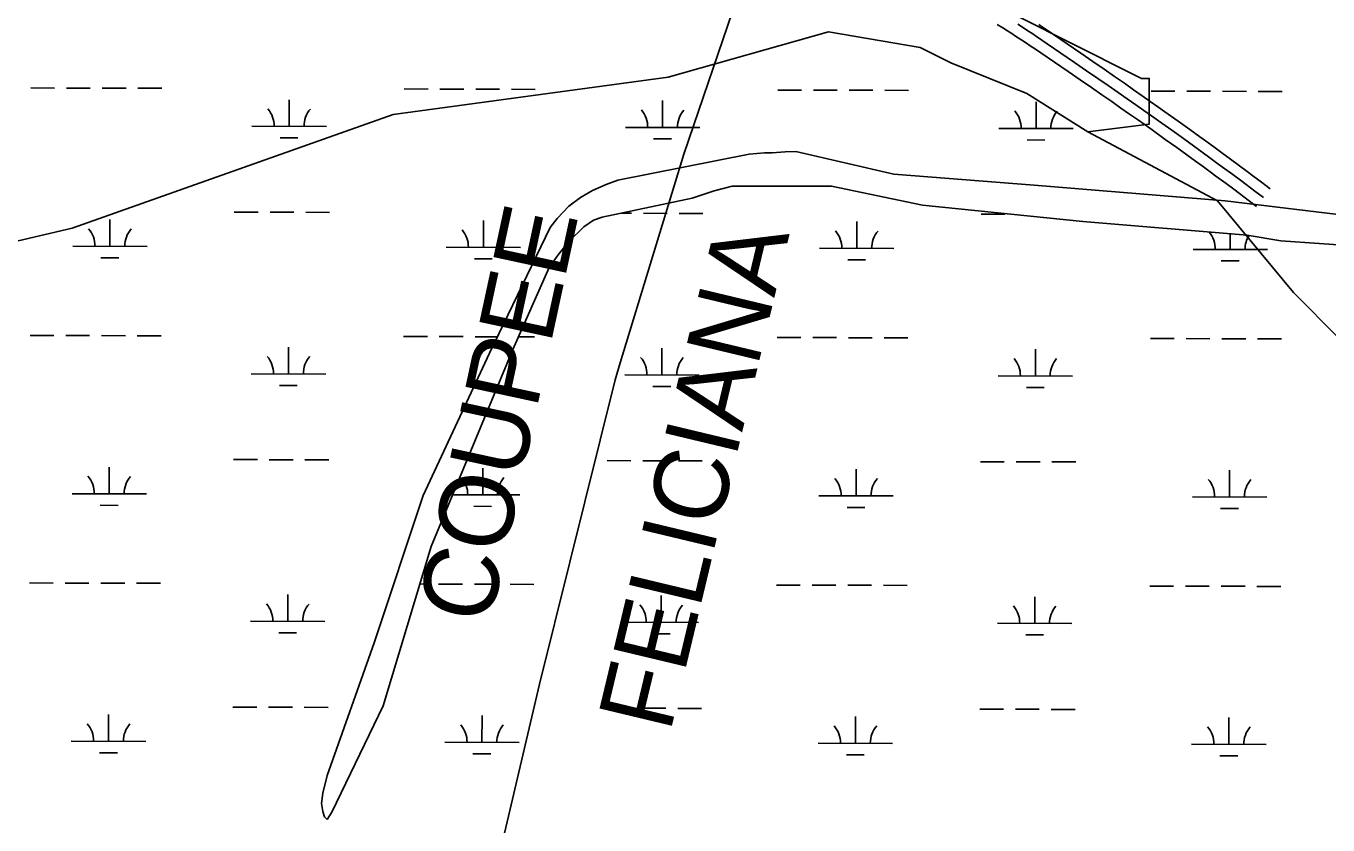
# Model space of a CAD drawing. Extents: x 3161615 to 3199515, y 867541 to 892976.
# Drawn here: x 3178180 to 3179930, y 873810 to 874884 of the extents above; entities that cross this region are included whole.
import ezdxf

# ---------------------------------------------------------------- set-up
doc = ezdxf.new("R2010")
doc.units = 0
for name, color, linetype in [('V-ROAD-CNTR', 7, 'Continuous'), ('V-TOPO-BNDY', 7, 'Continuous'), ('V-TOPO-GNAM-IDEN', 7, 'Continuous'), ('V-TOPO-SHOR', 7, 'Continuous'), ('V-WETL-SWMP', 7, 'Continuous')]:
    doc.layers.add(name, color=color, linetype=linetype)

msp = doc.modelspace()

# ---------------------------------------------------------------- linework, layer by layer
at = {"layer": 'V-ROAD-CNTR'}
for points in [[(3179485.3, 874885.7), (3179492.8, 874881), (3179499.3, 874876.9), (3179505, 874873.3), (3179509.9, 874870.1), (3179518.6, 874864.5), (3179525, 874860.3), (3179529.8, 874857.1), (3179537, 874852.3), (3179544.2, 874847.4), (3179580.9, 874822.2), (3179597, 874811.2), (3179612, 874800.8), (3179626.1, 874791.1), (3179639.3, 874781.9), (3179651.6, 874773.3), (3179663.2, 874765.2), (3179674, 874757.7), (3179684.1, 874750.5), (3179693.6, 874743.8), (3179711.3, 874731.2), (3179726.8, 874720.1), (3179740.3, 874710.4), (3179752.1, 874701.8), (3179762.5, 874694.3), (3179771.5, 874687.7), (3179779.3, 874681.9), (3179793.1, 874671.8), (3179803.3, 874664.1), (3179811, 874658.3), (3179822.5, 874649.6), (3179834, 874640.9)], [(3179513.1, 874886), (3179518.1, 874882.8), (3179526.8, 874877.1), (3179533.3, 874872.8), (3179538.2, 874869.6), (3179545.4, 874864.7), (3179552.7, 874859.8), (3179589.4, 874834.6), (3179605.5, 874823.5), (3179620.5, 874813.1), (3179634.6, 874803.4), (3179647.8, 874794.2), (3179660.2, 874785.6), (3179671.8, 874777.5), (3179682.6, 874769.9), (3179692.7, 874762.8), (3179702.2, 874756.1), (3179720, 874743.4), (3179735.6, 874732.3), (3179749.1, 874722.6), (3179761, 874714), (3179771.3, 874706.4), (3179780.3, 874699.8), (3179788.2, 874694), (3179802, 874683.8), (3179812.3, 874676.1), (3179820, 874670.3), (3179831.6, 874661.6), (3179843.1, 874652.8)], [(3179541.5, 874885.4), (3179546.5, 874882.1), (3179553.8, 874877.2), (3179561.1, 874872.2), (3179597.9, 874846.9), (3179614, 874835.9), (3179629.1, 874825.5), (3179643.2, 874815.7), (3179656.4, 874806.5), (3179668.8, 874797.9), (3179680.4, 874789.8), (3179691.2, 874782.2), (3179701.4, 874775), (3179710.9, 874768.3), (3179728.7, 874755.7), (3179744.3, 874744.5), (3179757.9, 874734.7), (3179769.8, 874726.1), (3179780.2, 874718.6), (3179789.2, 874711.9), (3179797.1, 874706.1), (3179811, 874695.8), (3179821.3, 874688.1), (3179829.1, 874682.3), (3179840.7, 874673.5), (3179852.2, 874664.7)]]:
    msp.add_lwpolyline(points, dxfattribs=at)
at = {"layer": 'V-TOPO-BNDY'}
for p, q in [((3179064.1, 874711.2), (3179152.6, 874969.8)), ((3178978.9, 874430.8), (3179064.1, 874711.2)), ((3178972, 874408), (3178978.9, 874430.8)), ((3178911.2, 874162.7), (3178972, 874408)), ((3178870.4, 873998.9), (3178911.2, 874162.7)), ((3178790.2, 873659.1), (3178870.4, 873998.9))]:
    msp.add_line(p, q, dxfattribs=at)
at = {"layer": 'V-TOPO-SHOR'}
for points in [[(3179310.9, 875132.1), (3179464.6, 875039.3), (3179464.5, 875008.5), (3179454.1, 874947), (3179474.5, 874916.1), (3179576.9, 874864.6), (3179679.4, 874813), (3179689.7, 874813), (3179689.6, 874802.7), (3179689.5, 874751.4), (3179607.4, 874741.4)], [(3178673.8, 874764.5), (3179043.3, 874814.7), (3179258.9, 874875.7), (3179382, 874854.8), (3179423, 874834.2), (3179525.4, 874792.9), (3179607.4, 874741.4), (3179781.5, 874648.5), (3179883.8, 874525.1), (3179945.2, 874463.4), (3179996.4, 874412), (3180057.8, 874381), (3180160.4, 874370.5), (3180386.1, 874369.9), (3180468.1, 874349.1), (3180519.5, 874369.5), (3180591.5, 874420.6), (3180632.7, 874502.5)], [(3178673.8, 874764.5), (3178242.4, 874611.8), (3178067.9, 874571.2), (3177842.1, 874530.8), (3177800.9, 874469.3), (3177728.9, 874418.2), (3177677.4, 874326), (3177595.1, 874244.2), (3177533.2, 874121.2), (3177481.5, 873988), (3177450.6, 873947), (3177378.3, 873793.3), (3177305.9, 873567.8), (3177233.7, 873424.4), (3177161.6, 873342.5), (3177089.6, 873270.9), (3176966.3, 873209.7), (3176915, 873189.3), (3176894.3, 873148.3), (3176857.1, 873094.3)]]:
    msp.add_lwpolyline(points, dxfattribs=at)
at = {"layer": 'V-WETL-SWMP'}
for p, q in [((3178186.6, 874800.3), (3178218.6, 874800.2)), ((3178234.6, 874800.1), (3178266.6, 874800)), ((3178282.6, 874800), (3178314.6, 874799.9)), ((3178330.6, 874799.9), (3178362.6, 874799.8)), ((3178688.5, 874798.9), (3178720.5, 874798.8)), ((3178736.5, 874798.7), (3178768.5, 874798.6)), ((3178784.5, 874798.6), (3178816.5, 874798.5)), ((3178832.5, 874798.5), (3178864.5, 874798.4)), ((3179190.4, 874797.5), (3179222.4, 874797.4)), ((3179238.4, 874797.3), (3179270.4, 874797.3)), ((3179286.4, 874797.2), (3179318.4, 874797.1)), ((3179334.4, 874797.1), (3179366.4, 874797)), ((3179692.3, 874796.1), (3179724.3, 874796)), ((3179740.3, 874796), (3179772.3, 874795.9)), ((3179788.3, 874795.8), (3179820.3, 874795.7)), ((3179836.3, 874795.7), (3179868.3, 874795.6)), ((3178533.8, 874748.5), (3178533.9, 874784.5)), ((3179035.7, 874747.2), (3179035.8, 874783.2)), ((3179537.6, 874745.8), (3179537.7, 874781.8)), ((3178483.8, 874748.7), (3178583.8, 874748.4)), ((3178985.7, 874747.3), (3179085.7, 874747)), ((3179487.6, 874745.9), (3179587.6, 874745.6)), ((3178521.7, 874733.2), (3178545.7, 874733.1)), ((3179023.7, 874731.8), (3179047.7, 874731.7)), ((3179525.6, 874730.4), (3179549.6, 874730.3)), ((3179152.1, 874711.1), (3178975.5, 874676.5)), ((3179172.8, 874713), (3179152.1, 874711.1)), ((3179183, 874713), (3179172.8, 874713)), ((3179200.4, 874714.3), (3179183, 874713)), ((3179214.8, 874714.8), (3179200.4, 874714.3)), ((3179346.7, 874684.5), (3179214.8, 874714.8)), ((3178975.5, 874676.5), (3178959.7, 874670.7)), ((3179534.9, 874669.4), (3179346.7, 874684.5)), ((3178941.3, 874662.4), (3178925.3, 874653.2)), ((3178959.7, 874670.7), (3178941.3, 874662.4)), ((3179075.6, 874651.9), (3179105, 874662.1)), ((3179105, 874662.1), (3179129.3, 874668.3)), ((3179129.3, 874668.3), (3179262.9, 874668.1)), ((3179262.9, 874668.1), (3179385.1, 874642.7)), ((3179791.6, 874648.7), (3179534.9, 874669.4)), ((3178909.9, 874641.4), (3178894.1, 874624.7)), ((3178925.3, 874653.2), (3178909.9, 874641.4)), ((3178954.4, 874626.5), (3179075.6, 874651.9)), ((3179385.1, 874642.7), (3179600.3, 874620.6)), ((3180024.4, 874620.3), (3179791.6, 874648.7)), ((3178292.9, 874587.4), (3178293, 874623.4)), ((3178460.1, 874633.3), (3178492.1, 874633.2)), ((3178508.1, 874633.2), (3178540.1, 874633.1)), ((3178556.1, 874633.1), (3178588.1, 874633)), ((3178794.8, 874586), (3178794.9, 874622)), ((3178894.1, 874624.7), (3178884.5, 874612.7)), ((3178929.8, 874613.8), (3178942.9, 874622.4)), ((3178942.9, 874622.4), (3178954.4, 874626.5)), ((3178979.9, 874631.9), (3178994, 874631.8)), ((3179010, 874631.8), (3179042, 874631.7)), ((3179058, 874631.7), (3179090, 874631.6)), ((3179296.7, 874584.6), (3179296.8, 874620.6)), ((3179463.9, 874630.5), (3179495.9, 874630.5)), ((3179600.3, 874620.6), (3179821.4, 874602.4)), ((3178884.5, 874612.7), (3178803, 874443.7)), ((3178909.9, 874593.8), (3178929.8, 874613.8)), ((3179798.6, 874583.2), (3179798.6, 874604.3)), ((3178242.9, 874587.5), (3178342.9, 874587.2)), ((3178744.8, 874586.1), (3178844.8, 874585.8)), ((3178895.3, 874575.8), (3178909.9, 874593.8)), ((3179821.4, 874602.4), (3179866.8, 874594.6)), ((3179866.8, 874594.6), (3180086.2, 874579.7)), ((3178280.8, 874572), (3178304.8, 874571.9)), ((3178782.7, 874570.6), (3178806.7, 874570.5)), ((3178883.3, 874558.8), (3178895.3, 874575.8)), ((3179246.7, 874584.7), (3179346.7, 874584.4)), ((3179284.6, 874569.2), (3179308.6, 874569.1)), ((3179748.6, 874583.3), (3179848.6, 874583.1)), ((3178834.6, 874448.6), (3178883.3, 874558.8)), ((3179786.5, 874567.8), (3179810.5, 874567.7)), ((3178185.7, 874467.6), (3178217.7, 874467.5)), ((3178233.7, 874467.4), (3178265.7, 874467.4)), ((3178281.7, 874467.3), (3178313.7, 874467.2)), ((3178329.7, 874467.2), (3178361.7, 874467.1)), ((3178687.6, 874466.2), (3178719.6, 874466.1)), ((3178735.6, 874466.1), (3178767.6, 874466)), ((3178783.6, 874465.9), (3178813.7, 874465.8)), ((3178842.2, 874465.8), (3178863.6, 874465.7)), ((3179189.5, 874464.8), (3179221.5, 874464.7)), ((3179237.5, 874464.7), (3179269.5, 874464.6)), ((3179285.5, 874464.5), (3179317.5, 874464.4)), ((3179333.5, 874464.4), (3179365.5, 874464.3)), ((3179691.4, 874463.4), (3179723.4, 874463.3)), ((3179739.4, 874463.3), (3179771.4, 874463.2)), ((3179787.4, 874463.2), (3179819.4, 874463.1)), ((3179835.4, 874463), (3179867.4, 874462.9)), ((3178532.9, 874415.9), (3178533, 874451.9)), ((3178724.7, 874184), (3178834.6, 874448.6)), ((3179034.8, 874414.5), (3179034.9, 874450.5)), ((3179536.7, 874413.1), (3179536.8, 874449.1)), ((3178803, 874443.7), (3178713.8, 874252.6)), ((3178482.9, 874416), (3178582.9, 874415.7)), ((3178984.8, 874414.6), (3179084.8, 874414.4)), ((3179486.7, 874413.2), (3179586.7, 874413)), ((3178520.8, 874400.5), (3178544.8, 874400.4)), ((3179022.7, 874399.1), (3179046.7, 874399)), ((3179524.6, 874397.7), (3179548.6, 874397.6)), ((3178292, 874254.7), (3178292, 874290.7)), ((3178459.1, 874300.6), (3178491.1, 874300.6)), ((3178507.1, 874300.5), (3178539.1, 874300.4)), ((3178555.1, 874300.4), (3178587.1, 874300.3)), ((3178793.9, 874253.3), (3178794, 874289.3)), ((3178961, 874299.3), (3178993, 874299.2)), ((3179009, 874299.1), (3179041, 874299)), ((3179057, 874299), (3179089, 874298.9)), ((3179463, 874297.9), (3179495, 874297.8)), ((3179511, 874297.7), (3179543, 874297.7)), ((3179559, 874297.6), (3179591, 874297.5)), ((3179295.8, 874251.9), (3179295.9, 874287.9)), ((3179797.7, 874250.5), (3179797.8, 874286.5)), ((3178242, 874254.8), (3178342, 874254.5)), ((3178753.5, 874253.4), (3178843.9, 874253.2)), ((3178279.9, 874239.3), (3178303.9, 874239.2)), ((3178713.8, 874252.6), (3178648.1, 874054.6)), ((3178781.8, 874237.9), (3178805.8, 874237.8)), ((3179245.8, 874252), (3179345.8, 874251.8)), ((3179283.7, 874236.5), (3179307.7, 874236.4)), ((3179747.7, 874250.7), (3179847.7, 874250.4)), ((3179785.6, 874235.1), (3179809.6, 874235.1)), ((3178660.1, 873969.5), (3178724.7, 874184)), ((3178184.8, 874134.9), (3178216.8, 874134.8)), ((3178232.8, 874134.8), (3178264.8, 874134.7)), ((3178280.8, 874134.6), (3178312.8, 874134.5)), ((3178328.8, 874134.5), (3178360.8, 874134.4)), ((3178709.5, 874133.5), (3178718.7, 874133.4)), ((3178734.7, 874133.4), (3178766.7, 874133.3)), ((3178782.7, 874133.3), (3178814.7, 874133.2)), ((3178830.7, 874133.1), (3178862.7, 874133)), ((3179188.6, 874132.1), (3179220.6, 874132)), ((3179236.6, 874132), (3179268.6, 874131.9)), ((3179284.6, 874131.9), (3179316.6, 874131.8)), ((3179332.6, 874131.7), (3179364.6, 874131.6)), ((3179690.5, 874130.7), (3179722.5, 874130.7)), ((3179738.5, 874130.6), (3179770.5, 874130.5)), ((3179786.5, 874130.5), (3179818.5, 874130.4)), ((3178531.9, 874083.2), (3178532, 874119.2)), ((3179033.9, 874081.8), (3179034, 874117.8)), ((3179535.8, 874080.4), (3179535.9, 874116.4)), ((3179834.5, 874130.3), (3179866.5, 874130.3)), ((3178481.9, 874083.3), (3178581.9, 874083.1)), ((3178983.9, 874082), (3179083.9, 874081.7)), ((3179485.8, 874080.6), (3179585.8, 874080.3)), ((3178519.9, 874067.8), (3178543.9, 874067.7)), ((3179021.8, 874066.4), (3179045.8, 874066.4)), ((3179523.7, 874065), (3179547.7, 874065)), ((3178648.1, 874054.6), (3178585.1, 873875.9)), ((3178291, 873922), (3178291.1, 873958)), ((3178458.2, 873968), (3178490.2, 873967.9)), ((3178506.2, 873967.8), (3178538.2, 873967.8)), ((3178554.2, 873967.7), (3178586.2, 873967.6)), ((3178591.4, 873826.8), (3178660.1, 873969.5)), ((3178792.9, 873920.6), (3178793, 873956.6)), ((3178960.1, 873966.6), (3178992.1, 873966.5)), ((3179008.1, 873966.5), (3179040.1, 873966.4)), ((3179056.1, 873966.3), (3179088.1, 873966.2)), ((3179462, 873965.2), (3179494, 873965.1)), ((3179510, 873965.1), (3179542, 873965)), ((3179558, 873964.9), (3179590, 873964.8)), ((3179294.8, 873919.2), (3179294.9, 873955.2)), ((3179796.7, 873917.8), (3179796.8, 873953.8)), ((3178241, 873922.1), (3178341, 873921.9)), ((3178742.9, 873920.8), (3178842.9, 873920.5)), ((3178279, 873906.6), (3178303, 873906.5)), ((3178780.9, 873905.2), (3178804.9, 873905.2)), ((3179244.8, 873919.4), (3179344.8, 873919.1)), ((3179282.8, 873903.8), (3179306.8, 873903.8)), ((3179746.7, 873918), (3179846.7, 873917.7)), ((3179784.7, 873902.4), (3179808.7, 873902.4)), ((3178585.1, 873875.9), (3178579.2, 873852.5)), ((3178579.2, 873852.5), (3178577.3, 873838.5)), ((3178577.3, 873838.5), (3178579, 873827.7)), ((3178579, 873827.7), (3178581.3, 873820.5)), ((3178581.3, 873820.5), (3178584.8, 873816.9)), ((3178584.8, 873816.9), (3178591.4, 873826.8))]:
    msp.add_line(p, q, dxfattribs=at)
for centre, start, end in [((3178478.5, 874749.2), 359.0699, 40.6135), ((3178589, 874748.9), 139.0699, 180.6135), ((3178980.5, 874747.8), 359.0699, 40.6135), ((3179090.9, 874747.5), 139.0699, 180.6135), ((3179482.4, 874746.4), 359.0699, 40.6135), ((3179592.8, 874746.1), 139.0699, 180.6135), ((3178237.6, 874588), 359.0699, 40.6135), ((3178348.1, 874587.7), 139.0699, 180.6135), ((3178739.5, 874586.6), 359.0699, 40.6135), ((3178850, 874586.3), 139.0699, 180.6135), ((3179241.4, 874585.2), 359.0699, 40.6135), ((3179351.9, 874584.9), 139.0699, 180.6135), ((3179743.3, 874583.8), 359.0699, 40.3523), ((3179853.8, 874583.5), 148.3195, 180.6135), ((3178477.6, 874416.5), 359.0699, 40.6135), ((3178588.1, 874416.2), 139.0699, 180.6135), ((3178979.5, 874415.1), 359.0699, 40.6135), ((3179090, 874414.8), 139.0699, 180.6135), ((3179481.4, 874413.7), 359.0699, 40.6135), ((3179591.9, 874413.4), 139.0699, 180.6135), ((3178236.7, 874255.3), 359.0699, 40.6135), ((3178347.2, 874255), 139.0699, 180.6135), ((3178738.6, 874253.9), 359.0699, 40.6135), ((3178849.1, 874253.6), 139.0699, 180.6135), ((3179240.5, 874252.5), 359.0699, 40.6135), ((3179351, 874252.2), 139.0699, 180.6135), ((3179742.4, 874251.1), 359.0699, 40.6135), ((3179852.9, 874250.8), 139.0699, 180.6135), ((3178476.7, 874083.8), 359.0699, 40.6135), ((3178587.2, 874083.5), 139.0699, 180.6135), ((3178978.6, 874082.4), 359.0699, 40.6135), ((3179089.1, 874082.1), 139.0699, 180.6135), ((3179480.5, 874081.1), 359.0699, 40.6135), ((3179591, 874080.7), 139.0699, 180.6135), ((3178235.8, 873922.6), 359.0699, 40.6135), ((3178346.3, 873922.3), 139.0699, 180.6135), ((3178737.7, 873921.2), 359.0699, 40.6135), ((3178848.2, 873920.9), 139.0699, 180.6135), ((3179239.6, 873919.9), 359.0699, 40.6135), ((3179350.1, 873919.6), 139.0699, 180.6135), ((3179741.5, 873918.5), 359.0699, 40.6135), ((3179852, 873918.2), 139.0699, 180.6135)]:
    msp.add_arc(centre, 35.2, start, end, dxfattribs=at)

# ---------------------------------------------------------------- texts
at = {"layer": 'V-TOPO-GNAM-IDEN'}
for s, rotation, p in [('COUPEE', 77.833, (3178803.6, 874076.3)), ('FELICIANA', 76.5471, (3179045.7, 873932.2))]:
    msp.add_text(s, height=100, rotation=rotation, dxfattribs=at).set_placement(p)

doc.saveas('drawing.dxf')
